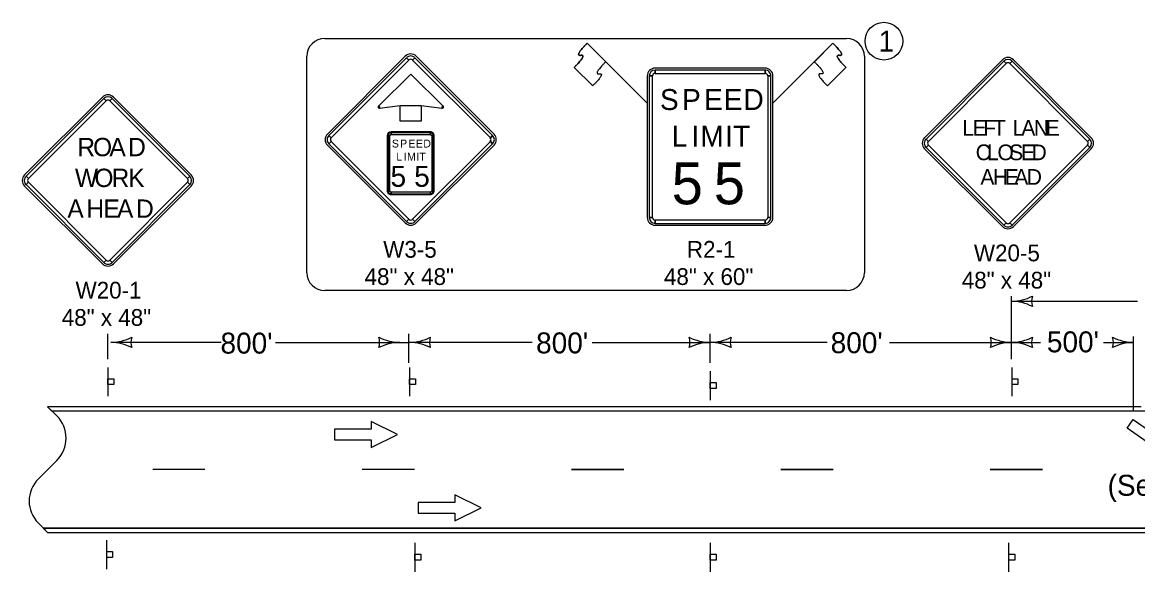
# Model space of a CAD drawing. Extents: x 10133 to 2270741, y 5363 to 1733450.
# Drawn here: x 24549 to 25614, y 11557 to 12081 of the extents above; entities that cross this region are included whole.
import ezdxf

# ---------------------------------------------------------------- set-up
doc = ezdxf.new("R2010")
doc.units = 0
for name, color, linetype in [('dsnNonPlotable', 7, 'Continuous'), ('dsnShtPlotShapeBatchPrint', 7, 'Continuous'), ('dsnStdBorder', 7, 'Continuous'), ('Level 12', 7, 'Continuous'), ('Level 2', 7, 'Continuous')]:
    doc.layers.add(name, color=color, linetype=linetype)

msp = doc.modelspace()

# ---------------------------------------------------------------- linework, layer by layer
at = {"layer": 'dsnNonPlotable'}
for p, q in [((24581.6, 11705.5), (24572.8, 11714.3)), ((24576.8, 11710.3), (26185, 11710.3)), ((25603.8, 11693.9), (25609.6, 11702.1)), ((25609.6, 11702.1), (25638.2, 11682)), ((25632.5, 11673.8), (25603.8, 11693.9)), ((24564, 11645.6), (24581.6, 11663.1)), ((24572.8, 11594.3), (24564, 11603.1))]:
    msp.add_line(p, q, dxfattribs=at)
for points in [[(24673.2, 11654.7), (24723.1, 11654.7)], [(24873.1, 11654.7), (24923.1, 11654.7)], [(25073.1, 11654.7), (25123.1, 11654.7)], [(25073.1, 11654.4), (25123.1, 11654.4)], [(25273.1, 11654.7), (25323.1, 11654.7)], [(25273.1, 11654.4), (25323.1, 11654.4)], [(25473, 11654.7), (25523, 11654.7)], [(25473, 11654.4), (25523, 11654.4)]]:
    msp.add_lwpolyline(points, dxfattribs=at)
for centre, start, end in [((24560.4, 11684.3), 315, 45), ((24585.2, 11624.3), 135, 225)]:
    msp.add_arc(centre, 30, start, end, dxfattribs=at)
at = {"layer": 'dsnShtPlotShapeBatchPrint'}
msp.add_circle((25371.5, 12063.2), 18, dxfattribs=at)
at = {"layer": 'dsnStdBorder'}
for p, q in [((25145.5, 12003.9), (25088.1, 12061.2)), ((25088.1, 12061.2), (25105.8, 12043.5)), ((25265.5, 12003.9), (25322.8, 12061.2)), ((25322.8, 12061.2), (25305.1, 12043.5)), ((24914.3, 12048.8), (24840, 11974.5)), ((24915.6, 12047.4), (24917.8, 12045.2)), ((24921.3, 12045.2), (24923.6, 12047.4)), ((24999.1, 11974.5), (24924.9, 12048.8)), ((25075.8, 12038.2), (25093.4, 12020.6)), ((25093.4, 12020.6), (25075.8, 12038.2)), ((25258, 12037.5), (25153, 12037.5)), ((25335.2, 12038.2), (25317.5, 12020.6)), ((25317.5, 12020.6), (25335.2, 12038.2)), ((25484.6, 12045.4), (25410.3, 11971.1)), ((25485.9, 12044), (25488.1, 12041.8)), ((25491.7, 12041.8), (25493.9, 12044)), ((25569.4, 11971.1), (25495.2, 12045.4)), ((25145.5, 12030), (25145.5, 11895)), ((25147.3, 12030), (25150.5, 12030)), ((25153, 12032.5), (25153, 12035.6)), ((25258, 12035.6), (25258, 12032.5)), ((25260.5, 12030), (25263.6, 12030)), ((25265.5, 11895), (25265.5, 12030)), ((24625.1, 12009.8), (24550.8, 11935.5)), ((24626.4, 12008.5), (24628.6, 12006.3)), ((24632.1, 12006.3), (24634.4, 12008.5)), ((24709.9, 11935.5), (24635.7, 12009.8)), ((24889.6, 12000.5), (24888.7, 12001.3)), ((24889.7, 11999.2), (24889.6, 12000.5)), ((24949.6, 12000.5), (24949.4, 11999.2)), ((24950.5, 12001.3), (24949.6, 12000.5)), ((24843.6, 11971), (24841.4, 11973.2)), ((24897.1, 11973), (24897.1, 11920.5)), ((24898, 11973), (24899.6, 11973)), ((24938.3, 11976.7), (24900.8, 11976.7)), ((24900.8, 11974.2), (24900.8, 11975.8)), ((24938.3, 11975.8), (24938.3, 11974.2)), ((24939.6, 11973), (24941.1, 11973)), ((24942.1, 11920.5), (24942.1, 11973)), ((24997.8, 11973.2), (24995.6, 11971)), ((24840, 11963.9), (24914.3, 11889.7)), ((24841.4, 11965.2), (24843.6, 11967.4)), ((24924.9, 11889.7), (24999.1, 11963.9)), ((24995.6, 11967.4), (24997.8, 11965.2)), ((25413.9, 11967.6), (25411.7, 11969.8)), ((25411.7, 11961.8), (25413.9, 11964)), ((25568.1, 11969.8), (25565.9, 11967.6)), ((25565.9, 11964), (25568.1, 11961.8)), ((25410.3, 11960.5), (25484.6, 11886.3)), ((25495.2, 11886.3), (25569.4, 11960.5)), ((24554.4, 11932), (24552.2, 11934.2)), ((24708.6, 11934.2), (24706.4, 11932)), ((24550.8, 11924.9), (24625.1, 11850.7)), ((24552.2, 11926.3), (24554.4, 11928.5)), ((24635.7, 11850.7), (24709.9, 11924.9)), ((24706.4, 11928.5), (24708.6, 11926.3)), ((24899.6, 11920.5), (24898, 11920.5)), ((24941.1, 11920.5), (24939.6, 11920.5)), ((24900.8, 11917.6), (24900.8, 11919.2)), ((24900.8, 11916.7), (24938.3, 11916.7)), ((24938.3, 11919.2), (24938.3, 11917.6)), ((24917.8, 11893.2), (24915.6, 11891)), ((24923.6, 11891), (24921.3, 11893.2)), ((25150.5, 11895), (25147.3, 11895)), ((25153, 11889.3), (25153, 11892.5)), ((25258, 11892.5), (25258, 11889.3)), ((25263.6, 11895), (25260.5, 11895)), ((25488.1, 11889.8), (25485.9, 11887.6)), ((25493.9, 11887.6), (25491.7, 11889.8)), ((25153, 11887.5), (25258, 11887.5)), ((24628.6, 11854.2), (24626.4, 11852)), ((24634.4, 11852), (24632.1, 11854.2)), ((24630.3, 11751.8), (24630.3, 11724.3)), ((24918.3, 11751.8), (24918.3, 11724.3)), ((25493.7, 11751.8), (25493.7, 11724.3)), ((25205.5, 11748.1), (25205.5, 11720.6)), ((24629.1, 11586.9), (24629.1, 11559.4)), ((24923.4, 11584.3), (24923.4, 11556.8)), ((25205.5, 11584.3), (25205.5, 11556.8)), ((25490.6, 11584.3), (25490.6, 11556.8))]:
    msp.add_line(p, q, dxfattribs=at)
for points in [[(24837.4, 12065.9), (25335.8, 12065.9)], [(24820.4, 11842.2), (24820.4, 12048.8)], [(25352.8, 12048.8), (25352.8, 11842.2)], [(25335.8, 11825.2), (24837.4, 11825.2)], [(24846.8, 11692.8), (24846.8, 11682.8), (24881.8, 11682.8), (24881.8, 11675.3), (24906.8, 11687.8), (24881.8, 11700.3), (24881.8, 11692.8), (24846.8, 11692.8)], [(24926.8, 11622.8), (24926.8, 11612.8), (24961.8, 11612.8), (24961.8, 11605.3), (24986.8, 11617.8), (24961.8, 11630.3), (24961.8, 11622.8), (24926.8, 11622.8)]]:
    msp.add_lwpolyline(points, dxfattribs=at)
for points in [[(24915.6, 12047.4), (24841.4, 11973.2), (24843.6, 11971), (24917.8, 12045.2), (24915.6, 12047.4)], [(24997.8, 11973.2), (24923.6, 12047.4), (24921.3, 12045.2), (24995.6, 11971), (24997.8, 11973.2)], [(25485.9, 12044), (25411.7, 11969.8), (25413.9, 11967.6), (25488.1, 12041.8), (25485.9, 12044)], [(25568.1, 11969.8), (25493.9, 12044), (25491.7, 12041.8), (25565.9, 11967.6), (25568.1, 11969.8)], [(24919.6, 12031.7), (24888.7, 12001.3), (24889.6, 12000.5), (24889.7, 11999.2), (24909.6, 12001.7), (24929.6, 12001.7), (24949.4, 11999.2), (24949.6, 12000.5), (24950.5, 12001.3), (24919.6, 12031.7)], [(25147.3, 12030), (25147.3, 11895), (25150.5, 11895), (25150.5, 12030), (25147.3, 12030)], [(25258, 12035.6), (25153, 12035.6), (25153, 12032.5), (25258, 12032.5), (25258, 12035.6)], [(25263.6, 11895), (25263.6, 12030), (25260.5, 12030), (25260.5, 11895), (25263.6, 11895)], [(24626.4, 12008.5), (24552.2, 11934.2), (24554.4, 11932), (24628.6, 12006.3), (24626.4, 12008.5)], [(24708.6, 11934.2), (24634.4, 12008.5), (24632.1, 12006.3), (24706.4, 11932), (24708.6, 11934.2)], [(24929.6, 11986.7), (24909.6, 11986.7), (24909.6, 12001.7), (24929.6, 12001.7), (24929.6, 11986.7)], [(24898, 11973), (24898, 11920.5), (24899.6, 11920.5), (24899.6, 11973), (24898, 11973)], [(24938.3, 11975.8), (24900.8, 11975.8), (24900.8, 11974.2), (24938.3, 11974.2), (24938.3, 11975.8)], [(24941.1, 11920.5), (24941.1, 11973), (24939.6, 11973), (24939.6, 11920.5), (24941.1, 11920.5)], [(24841.4, 11965.2), (24915.6, 11891), (24917.8, 11893.2), (24843.6, 11967.4), (24841.4, 11965.2)], [(24923.6, 11891), (24997.8, 11965.2), (24995.6, 11967.4), (24921.3, 11893.2), (24923.6, 11891)], [(25411.7, 11961.8), (25485.9, 11887.6), (25488.1, 11889.8), (25413.9, 11964), (25411.7, 11961.8)], [(25493.9, 11887.6), (25568.1, 11961.8), (25565.9, 11964), (25491.7, 11889.8), (25493.9, 11887.6)], [(24552.2, 11926.3), (24626.4, 11852), (24628.6, 11854.2), (24554.4, 11928.5), (24552.2, 11926.3)], [(24634.4, 11852), (24708.6, 11926.3), (24706.4, 11928.5), (24632.1, 11854.2), (24634.4, 11852)], [(24900.8, 11917.6), (24938.3, 11917.6), (24938.3, 11919.2), (24900.8, 11919.2), (24900.8, 11917.6)], [(25153, 11889.3), (25258, 11889.3), (25258, 11892.5), (25153, 11892.5), (25153, 11889.3)], [(24630.4, 11735.4), (24630.4, 11741), (24636, 11741), (24636, 11735.4)], [(24918.4, 11735.4), (24918.4, 11741), (24924, 11741), (24924, 11735.4)], [(25493.8, 11735.4), (25493.8, 11741), (25499.5, 11741), (25499.5, 11735.4)], [(25205.6, 11731.7), (25205.6, 11737.3), (25211.2, 11737.3), (25211.2, 11731.7)], [(24629.2, 11570.4), (24629.2, 11576), (24634.8, 11576), (24634.8, 11570.4)], [(24923.5, 11567.9), (24923.5, 11573.5), (24929.1, 11573.5), (24929.1, 11567.9)], [(25205.6, 11567.9), (25205.6, 11573.5), (25211.2, 11573.5), (25211.2, 11567.9)], [(25490.7, 11567.9), (25490.7, 11573.5), (25496.4, 11573.5), (25496.4, 11567.9)]]:
    msp.add_lwpolyline(points, close=True, dxfattribs=at)
for centre, radius, start, end in [((24837.4, 12048.8), 17, 90, 180), ((25335.8, 12048.8), 17, 0, 90), ((24919.6, 12043.5), 7.5, 45, 134.9997), ((24919.6, 12043.5), 5.62, 45, 134.9997), ((25489.9, 12040.1), 7.5, 45, 134.9997), ((24919.6, 12043.5), 2.5, 45, 134.9997), ((25153, 12030), 7.5, 90.0002, 179.9998), ((25258, 12030), 7.5, 0, 90.0002), ((25489.9, 12040.1), 5.62, 45, 134.9997), ((25489.9, 12040.1), 2.5, 45, 134.9997), ((25153, 12030), 5.62, 90.0002, 179.9998), ((25153, 12030), 2.5, 90.0002, 179.9998), ((25258, 12030), 5.62, 0, 90.0002), ((25258, 12030), 2.5, 0, 90.0002), ((24630.4, 12004.5), 7.5, 45, 134.9997), ((24630.4, 12004.5), 5.62, 45, 134.9997), ((24630.4, 12004.5), 2.5, 45, 134.9997), ((24889.6, 12000.5), 1.25, 134.9997, 277.1529), ((24949.6, 12000.5), 1.25, 262.8473, 44.9998), ((24845.3, 11969.2), 7.5, 134.9997, 225), ((24845.3, 11969.2), 5.62, 134.9997, 225), ((24900.8, 11973), 3.75, 90.0002, 179.9998), ((24900.8, 11973), 2.81, 90.0002, 179.9998), ((24900.8, 11973), 1.25, 90.0002, 179.9998), ((24938.3, 11973), 3.75, 0, 90.0002), ((24938.3, 11973), 2.81, 0, 90.0002), ((24938.3, 11973), 1.25, 0, 90.0002), ((24993.8, 11969.2), 5.62, 315.0002, 44.9998), ((24993.8, 11969.2), 7.5, 315.0002, 44.9998), ((24845.3, 11969.2), 2.5, 134.9997, 225), ((24993.8, 11969.2), 2.5, 315.0002, 44.9998), ((25415.6, 11965.8), 7.5, 134.9997, 225), ((25415.6, 11965.8), 5.62, 134.9997, 225), ((25415.6, 11965.8), 2.5, 134.9997, 225), ((25564.1, 11965.8), 2.5, 315.0002, 44.9998), ((25564.1, 11965.8), 5.62, 315.0002, 44.9998), ((25564.1, 11965.8), 7.5, 315.0002, 44.9998), ((24556.1, 11930.2), 7.5, 134.9997, 225), ((24556.1, 11930.2), 5.62, 134.9997, 225), ((24556.1, 11930.2), 2.5, 134.9997, 225), ((24704.6, 11930.2), 2.5, 315.0002, 44.9998), ((24704.6, 11930.2), 5.62, 315.0002, 44.9998), ((24704.6, 11930.2), 7.5, 315.0002, 44.9998), ((24900.8, 11920.5), 3.75, 179.9998, 270.0001), ((24900.8, 11920.5), 2.81, 179.9998, 270.0001), ((24900.8, 11920.5), 1.25, 179.9998, 270.0001), ((24938.3, 11920.5), 3.75, 270.0001, 0.0003), ((24938.3, 11920.5), 2.81, 270.0001, 0.0003), ((24938.3, 11920.5), 1.25, 270.0001, 0.0003), ((24919.6, 11895), 7.5, 225, 315.0002), ((24919.6, 11895), 5.62, 225, 315.0002), ((24919.6, 11895), 2.5, 225, 315.0002), ((25153, 11895), 7.5, 179.9998, 270.0001), ((25153, 11895), 5.62, 179.9998, 270.0001), ((25153, 11895), 2.5, 179.9998, 270.0001), ((25258, 11895), 7.5, 270.0001, 0.0003), ((25258, 11895), 5.62, 270.0001, 0.0003), ((25258, 11895), 2.5, 270.0001, 0.0003), ((25489.9, 11891.6), 5.62, 225, 315.0002), ((25489.9, 11891.6), 2.5, 225, 315.0002), ((25489.9, 11891.6), 7.5, 225, 315.0002), ((24630.4, 11856), 7.5, 225, 315.0002), ((24630.4, 11856), 5.62, 225, 315.0002), ((24630.4, 11856), 2.5, 225, 315.0002), ((24837.4, 11842.2), 17, 180, 270), ((25335.8, 11842.2), 17, 270, 0)]:
    msp.add_arc(centre, radius, start, end, dxfattribs=at)
for points in [[(25088.1, 12061.2), (25075.8, 12048.8), (25088.1, 12050.6), (25075.8, 12038.2)], [(25075.8, 12038.2), (25088.1, 12050.6), (25075.8, 12048.8), (25088.1, 12061.2)], [(25322.8, 12061.2), (25335.2, 12048.8), (25322.8, 12050.6), (25335.2, 12038.2)], [(25335.2, 12038.2), (25322.8, 12050.6), (25335.2, 12048.8), (25322.8, 12061.2)], [(25105.8, 12043.5), (25093.4, 12031.2), (25105.8, 12032.9), (25093.4, 12020.6)], [(25105.8, 12043.5), (25093.4, 12031.2), (25105.8, 12032.9), (25093.4, 12020.6)], [(25305.1, 12043.5), (25317.5, 12031.2), (25305.1, 12032.9), (25317.5, 12020.6)], [(25305.1, 12043.5), (25317.5, 12031.2), (25305.1, 12032.9), (25317.5, 12020.6)]]:
    msp.add_open_spline(points, degree=2, dxfattribs=at)
at = {"layer": 'Level 12'}
for p, q in [((25493.1, 11814.9), (25613.8, 11814.9)), ((25493.3, 11759.8), (25493.3, 11819.9)), ((24630.3, 11759.8), (24630.3, 11783.9)), ((24917.9, 11756.1), (24917.9, 11783.9)), ((25205.5, 11756.1), (25205.5, 11783.9)), ((25609.9, 11710.1), (25609.9, 11781.3)), ((24738.5, 11775.7), (24633.1, 11775.7)), ((24790.5, 11775.7), (24917.9, 11775.7)), ((25035.7, 11775.7), (24917.9, 11775.7)), ((25093, 11775.7), (25205.5, 11775.7)), ((25317.3, 11775.7), (25205.5, 11775.7)), ((25376.7, 11775.7), (25493.1, 11775.7)), ((25493.9, 11775.7), (25521, 11775.7)), ((25581.3, 11775.7), (25609.9, 11775.7))]:
    msp.add_line(p, q, dxfattribs=at)
for centre, radius, start, end in [((25493.3, 11857.4), 42.5, 270, 298.0725), ((25493.3, 11772.4), 42.5, 61.9275, 90), ((25528.9, 11814.9), 16.4, 162.2666, 197.7334), ((24633.1, 11818.2), 42.5, 270, 298.0725), ((24633.1, 11733.2), 42.5, 61.9275, 90), ((24668.8, 11775.7), 16.4, 162.2666, 197.7334), ((24873.5, 11775.7), 16.4, 342.2666, 17.7334), ((24909.2, 11818.2), 42.5, 241.9275, 270), ((24909.2, 11733.2), 42.5, 90, 118.0725), ((24918.3, 11818.2), 42.5, 270, 298.0725), ((24918.3, 11733.2), 42.5, 61.9275, 90), ((24953.9, 11775.7), 16.4, 162.2666, 197.7334), ((25169.8, 11775.7), 16.4, 342.2666, 17.7334), ((25205.5, 11818.2), 42.5, 241.9275, 270), ((25205.5, 11733.2), 42.5, 90, 118.0725), ((25205.5, 11818.2), 42.5, 270, 298.0725), ((25205.5, 11733.2), 42.5, 61.9275, 90), ((25241.1, 11775.7), 16.4, 162.2666, 197.7334), ((25457.6, 11775.7), 16.4, 342.2666, 17.7334), ((25493.3, 11818.2), 42.5, 241.9275, 270), ((25493.3, 11733.2), 42.5, 90, 118.0725), ((25493.3, 11818.2), 42.5, 270, 298.0725), ((25493.3, 11733.2), 42.5, 61.9275, 90), ((25528.9, 11775.7), 16.4, 162.2666, 197.7334), ((25574.2, 11775.7), 16.4, 342.2666, 17.7334), ((25609.9, 11818.2), 42.5, 241.9275, 270), ((25609.9, 11733.2), 42.5, 90, 118.0725)]:
    msp.add_arc(centre, radius, start, end, dxfattribs=at)
at = {"layer": 'Level 2'}
for p, q in [((25617.3, 11714.3), (24572.8, 11714.3)), ((24572.8, 11714.3), (24581.6, 11705.5)), ((25609.9, 11714.3), (24572.8, 11714.3)), ((24576.8, 11710.3), (25609.9, 11710.3)), ((25609.9, 11710.3), (25609.9, 11714.3)), ((24581.6, 11663.1), (24564, 11645.6)), ((24564, 11603.1), (24568.8, 11598.3)), ((26364.3, 11598.3), (24568.8, 11598.3)), ((24568.8, 11598.3), (24572.8, 11594.3)), ((24568.8, 11598.3), (25786, 11598.3)), ((24572.8, 11594.3), (26391.1, 11594.3)), ((24572.8, 11594.3), (26362.6, 11594.3))]:
    msp.add_line(p, q, dxfattribs=at)
for points in [[(24572.8, 11714.3), (24576.8, 11710.4), (24576.8, 11710.3)], [(24568.8, 11598.3), (24568.8, 11598.3)], [(24568.8, 11598.3), (24568.8, 11598.3)]]:
    msp.add_lwpolyline(points, dxfattribs=at)
for centre, start, end in [((24560.4, 11684.3), 315, 45), ((24585.2, 11624.3), 135, 225)]:
    msp.add_arc(centre, 30, start, end, dxfattribs=at)

# ---------------------------------------------------------------- texts
at = {"layer": 'dsnShtPlotShapeBatchPrint'}
msp.add_text('1', height=20, dxfattribs=at).set_placement((25366.3, 12053.2))
at = {"layer": 'dsnStdBorder'}
for s, height, p in [('S', 20, (25157.6, 11997.5)), ('P', 20, (25178.7, 11997.5)), ('E', 20, (25199.8, 11997.5)), ('E', 20, (25218.6, 11997.5)), ('D', 20, (25237.4, 11997.5)), ('L', 15, (25446.3, 11973)), ('E', 15, (25456.3, 11973)), ('F', 15, (25466.3, 11973)), ('T', 15, (25475.5, 11973)), ('L', 15, (25494.4, 11973)), ('A', 15, (25502.7, 11973)), ('N', 15, (25514.6, 11973)), ('E', 15, (25526, 11973)), ('L', 20, (25168.8, 11962.5)), ('I', 20, (25187.6, 11962.5)), ('M', 20, (25196.2, 11962.5)), ('I', 20, (25219.8, 11962.5)), ('T', 20, (25227.4, 11962.5)), ('R', 17.5, (24601.2, 11953.4)), ('O', 17.5, (24616.2, 11953.4)), ('A', 17.5, (24631.8, 11953.4)), ('D', 17.5, (24649.7, 11953.4)), ('S', 7.5, (24901.6, 11961.7)), ('P', 7.5, (24909.5, 11961.7)), ('E', 7.5, (24917.4, 11961.7)), ('E', 7.5, (24924.5, 11961.7)), ('D', 7.5, (24931.6, 11961.7)), ('C', 15, (25459.1, 11949.6)), ('L', 15, (25469.8, 11949.6)), ('O', 15, (25479.9, 11949.6)), ('S', 15, (25491.1, 11949.6)), ('E', 15, (25502.4, 11949.6)), ('D', 15, (25512.5, 11949.6)), ('L', 7.5, (24905.8, 11949.2)), ('I', 7.5, (24912.9, 11949.2)), ('M', 7.5, (24916.1, 11949.2)), ('I', 7.5, (24925, 11949.2)), ('T', 7.5, (24927.8, 11949.2)), ('W', 17.5, (24598.9, 11924)), ('O', 17.5, (24617.5, 11924)), ('R', 17.5, (24633.9, 11924)), ('K', 17.5, (24649.8, 11924)), ('5', 20, (24900.3, 11924.2)), ('5', 20, (24922.9, 11924.2)), ('5', 40, (25168.8, 11907.5)), ('5', 40, (25209, 11907.5)), ('A', 15, (25463.6, 11926.1)), ('H', 15, (25475.5, 11926.1)), ('E', 15, (25486.9, 11926.1)), ('A', 15, (25496, 11926.1)), ('D', 15, (25507.9, 11926.1)), ('A', 17.5, (24591.7, 11894.6)), ('H', 17.5, (24609.9, 11894.6)), ('E', 17.5, (24626.1, 11894.6)), ('A', 17.5, (24639.1, 11894.6)), ('D', 17.5, (24657.3, 11894.6)), ('W3-5', 16, (24893.3, 11856.5)), ('R2-1', 16, (25183.3, 11856.5)), ('W20-5', 16, (25457.4, 11853.1)), ('48" x 48"', 16, (24875.5, 11830.5)), ('48" x 60"', 16, (25161.4, 11830.5)), ('48" x 48"', 16, (25445.8, 11827.1)), ('W20-1', 16, (24599.5, 11817.5)), ('48" x 48"', 16, (24586.3, 11791.5)), ('(See PM-111)', 20, (25585.1, 11629.3))]:
    msp.add_text(s, height=height, dxfattribs=at).set_placement(p)
at = {"layer": 'Level 12'}
for s, p in [("800'", (24737.9, 11765)), ("800'", (25039.3, 11765.2)), ("800'", (25320.6, 11765.4)), ("500'", (25527.1, 11766.2))]:
    msp.add_text(s, height=20, dxfattribs=at).set_placement(p)

doc.saveas('drawing.dxf')
